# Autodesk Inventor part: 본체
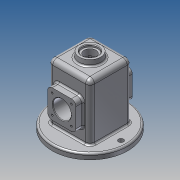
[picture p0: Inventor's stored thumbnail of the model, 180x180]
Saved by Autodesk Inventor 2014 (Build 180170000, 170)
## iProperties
Created: 2021-08
Part Number: 본체
Material: 알루미늄 6061
Document SubType Name: Modeling
Designer: kb542-04
Density: 2.71 g/cm^3
Appearance: 알루미늄 - 평지
Mass: 812.503 g
Surface Area: 933.129 cm^2
Volume: 299.816 cm^3
Author: kb542-04
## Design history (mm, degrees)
sketch "스케치2"
  geometry: C1 r 67 at (0, 0); 1 further point
  constraints: 1 centre point, 1 coincident
  dimensions: "d0" = 134 diameter of C1
extrude "돌출1" new body sketch "스케치2" distance "d1" = 10; taper "d2" = 0 deg
fillet "모깎기1" dims "d3" = 3
sketch "스케치3"
  geometry: L1 (37, -37)-(-37, -37); L2 (-37, -37)-(-37, 37); L3 (-37, 37)-(37, 37); L4 (37, 37)-(37, -37); L5 (37, -37)-(-37, 37); L6 (-37, -37)-(37, 37); 1 further point
  constraints: 12 end point, 2 midpoint, 2 parallel, 1 horizontal, 1 perpendicular
  dimensions: "d4" = 74 distance of L2.end L3.end; "d5" = 74 distance of L1.end L2.end
extrude "돌출2" join sketch "스케치3" distance "d6" = 100; taper "d7" = 0 deg
fillet "모깎기2" dims "d8" = 8
fillet "모깎기3" dims "d9" = 3
fillet "모깎기4" dims "d10" = 8
sketch "스케치7"
  geometry: C1 r 20 at (0, 0); 1 further point
  constraints: 1 centre point, 1 coincident
  dimensions: "d32" = 40 diameter of C1
extrude "돌출5" join sketch "스케치7" distance "d33" = 10; taper "d34" = -6 deg
sketch "스케치8"
  geometry: C1 r 14 at (0, 0); 1 further point
  constraints: 1 centre point, 1 coincident
  dimensions: "d35" = 28 diameter of C1
extrude "돌출6" cut sketch "스케치8" distance "d36" = 4; taper "d37" = 0 deg
sketch "스케치9"
  geometry: C1 r 10.5 at (0, 0); 1 further point
  constraints: 1 centre point, 1 coincident
  dimensions: "d38" = 21 diameter of C1
extrude "돌출7" cut sketch "스케치9" stored distance "d39" = 4; taper "d40" = 0 deg
sketch "스케치13"
  geometry: L1 (54, 17)-(4, 17); L2 (4, 17)-(4, 67); L3 (4, 67)-(54, 67); L4 (54, 67)-(54, 17); L5 (54, 17)-(4, 67); L6 (4, 17)-(54, 67); L7 (-38, -13)-(96, -13) reference; 4 further points
  constraints: 12 end point, 4 midpoint, 2 parallel, 1 horizontal, 1 perpendicular, 1 vertical alignment
  dimensions: "d47" = 50 distance of L2.end L3.end; "d48" = 50 distance of L1.end L2.end; "d49" = 55 distance from line of L7 point (29, 42)
extrude "돌출9" join sketch "스케치13" distance "d50" = 13; taper "d51" = 0 deg
fillet "모깎기9" dims "d56" = 8
fillet "모깎기10" dims "d57" = 3
sketch "스케치15"
  geometry: L1 (32, -32)-(-32, -32); L2 (-32, -32)-(-32, 32); L3 (-32, 32)-(32, 32); L4 (32, 32)-(32, -32); L5 (32, -32)-(-32, 32); L6 (-32, -32)-(32, 32); 1 further point
  constraints: 12 end point, 2 midpoint, 2 parallel, 1 horizontal, 1 perpendicular
  dimensions: "d58" = 64 distance of L2.end L3.end; "d59" = 64 distance of L1.end L2.end
extrude "돌출10" cut sketch "스케치15" distance "d60" = 105; taper "d61" = 0 deg
sketch "스케치16"
  geometry: L1 (0, -32)-(105, -32) reference; L2 (102, -37)-(13, -37) reference; L3 (79.856, -50.567)-(55, -50.567); L4 (55, -50.567)-(55, -15.891); L5 (55, -15.891)-(65.107, -15.891); L6 (65.107, -15.891)-(79.856, -32); L7 (79.856, -50.567)-(79.856, -32); L8 (0, 67)-(0, -67) reference; L9 (80, 50)-(80, 40) reference; L10 (0, 32)-(105, 32) reference; L11 (80, 32)-(77.452, 25); L12 (77.452, 25)-(55, 25); L13 (55, 25)-(55, 32); L14 (80, 32)-(55, 32); A1 r 3 centre (83, 40) between (80, 40) and (83, 37) reference; 1 further point
  constraints: 18 end point, 3 perpendicular, 3 point on line, 2 parallel
  dimensions: "d62" = 55 distance between parallel lines of L8 L4; "d64" = 110 deg angle of L10 L11; "d65" = 7 distance between parallel lines of L14 L12; "d101" = 25 distance between parallel lines of L9 L13; "d102" = 25 distance from line of L13 L11.start
revolve "회전2" sketch "스케치16" stored, may be unused: angle "d66" = 90 deg
sketch "스케치17"
  geometry: L1 (-38, -13)-(96, -13) reference; C1 r 16 at (29, 42); 2 further points
  constraints: 1 centre point, 1 midpoint, 1 vertical alignment
  dimensions: "d67" = 32 diameter of C1; "d68" = 55 distance from line of L1 C1.centre
extrude "돌출11" cut sketch "스케치17" stored distance "d69" = 105; taper "d70" = 0 deg
fillet "모깎기11" dims "d71" = 3
fillet "모깎기12" dims "d72" = 3
chamfer "모따기1" distance "d73" = 1; stored, may be unused: second distance "d74" = 2, angle "d75" = 45 deg
fillet "모깎기13" dims "d76" = 8
fillet "모깎기14" dims "d77" = 3
sketch "스케치19"
  geometry: L1 (46, 25)-(12, 25); L2 (12, 25)-(12, 59); L3 (12, 59)-(46, 59); L4 (46, 59)-(46, 25); L5 (46, 25)-(12, 59); L6 (12, 25)-(46, 59); L7 (-38, -13)-(96, -13) reference; 7 further points
  constraints: 12 end point, 4 coincident, 3 midpoint, 2 parallel, 1 horizontal, 1 perpendicular, 1 vertical alignment
  dimensions: "d78" = 34 distance of L2.end L3.end; "d79" = 34 distance of L1.end L2.end; "d80" = 55 distance from line of L7 point (29, 42)
hole "구멍2" sketch "스케치19" at (12, 59), (46, 59), (46, 25), (12, 25) diameter "d81" = 3.242; stored, may be unused: countersink angle "d85" = 90 deg, drill point angle "d87" = 118 deg; dims "d82" = 8, "d83" = 4, "d84" = 2, "d86" = 10
sketch "스케치20"
  geometry: C1 r 4.5 at (-55, 0); C2 r 4.5 at (55, 0); C3 r 55 at (0, 0); 1 further point
  constraints: 3 centre point, 2 horizontal alignment, 1 coincident
  dimensions: "d90" = 9 diameter of C1; "d91" = 9 diameter of C2; "d92" = 110 diameter of C3
extrude "돌출12" cut sketch "스케치20" distance "d93" = 10; taper "d94" = 0 deg
sketch "스케치21"
  geometry: L1 (-8, 89)-(-8, 0) reference; L2 (10.051, 107)-(47.949, 107) reference; 2 further points
  constraints: 1 other
  dimensions: "d95" = 37 distance from line of point (29, 79) L1; "d96" = 28 distance from line of point (29, 79) L2
feature "엠보싱1" sketch "스케치21" dims "d1" = 10, "d97" = 0.5, "d98" = 0
fillet "모깎기15" dims "d99" = 3
node "솔리드1"
mirror "대칭4"
mirror "대칭5"
